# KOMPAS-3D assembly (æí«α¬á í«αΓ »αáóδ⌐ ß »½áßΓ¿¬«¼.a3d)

Referenced files in D:\МОДЕЛЬ ТАНКА Т90\СБОРКИ\СБОРКА ЛИТЬЕ СТАРАЯ\: Сборка борт правый.a3d
Referenced files in D:\МОДЕЛЬ ТАНКА Т90\ДЕТАЛИ\КОРПУС\МЕТАЛЛ\КОРПУС ШТАМПОВКА\ПЛАСТИК\: борт пластик правый.m3d
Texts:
  Сборка борт правый с пластиком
